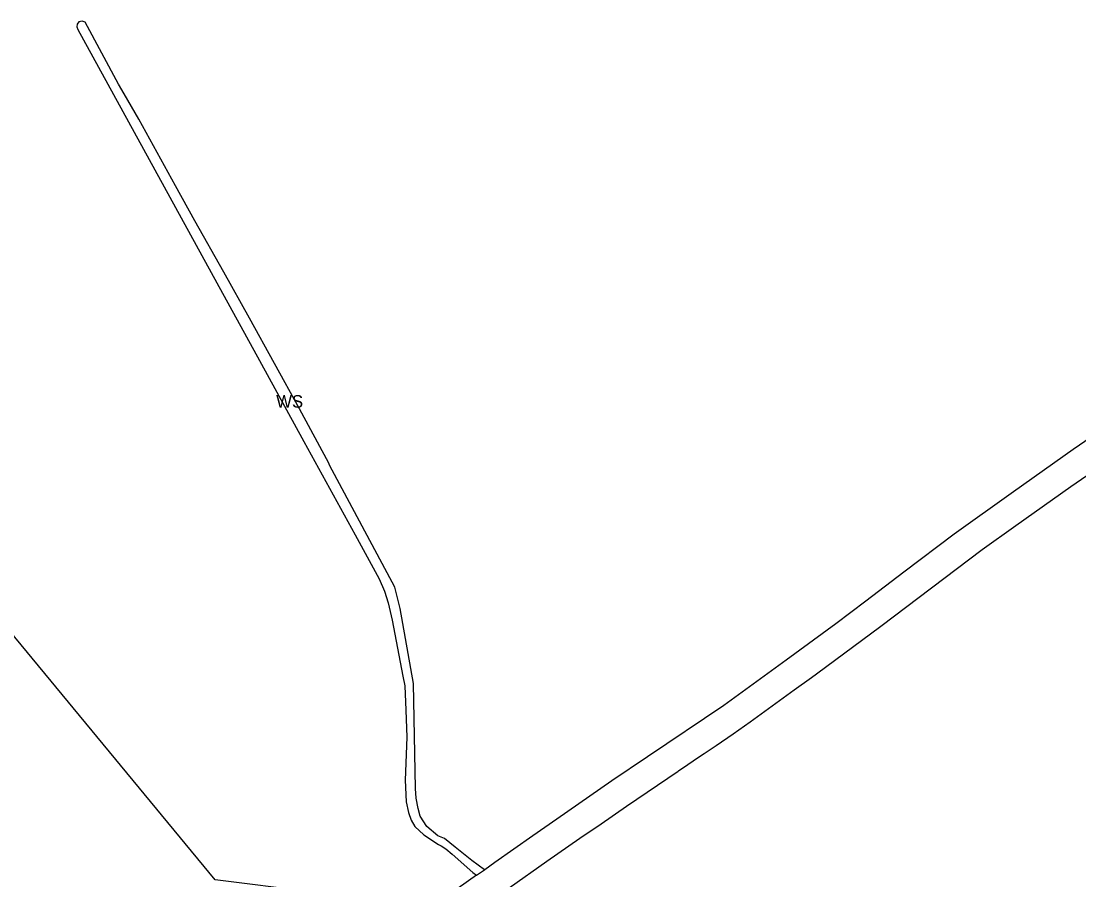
# Model space of a CAD drawing. Extents: x 7435758 to 7439981, y 5550649 to 5554049.
# Drawn here: x 7437632.3 to 7438071.5, y 5551959.4 to 5552316 of the extents above; entities that cross this region are included whole.
import ezdxf

# ---------------------------------------------------------------- set-up
doc = ezdxf.new("R2010")
doc.units = 0
doc.layers.add('linie_rozgraniczające', color=7, linetype='Continuous')
doc.layers.add('oznaczenia_przeznaczen', color=7, linetype='Continuous')

msp = doc.modelspace()

# ---------------------------------------------------------------- linework, layer by layer
at = {"layer": 'linie_rozgraniczające'}
for p, q in [((7437655.54, 5552314.73), (7437655.41, 5552313.64)), ((7437655.41, 5552313.64), (7437655.82, 5552312.48)), ((7437656.32, 5552315.76), (7437655.54, 5552314.73)), ((7437657.66, 5552315.99), (7437656.32, 5552315.76)), ((7437658.85, 5552315.59), (7437657.66, 5552315.99)), ((7437672.77, 5552289.88), (7437658.85, 5552315.59)), ((7437655.82, 5552312.48), (7437676.89, 5552274.12)), ((7437675.01, 5552285.82), (7437672.77, 5552289.88)), ((7437681.11, 5552275.27), (7437675.01, 5552285.82)), ((7437676.89, 5552274.12), (7437713.49, 5552207.37)), ((7437696.41, 5552247.65), (7437681.11, 5552275.27)), ((7437704.46, 5552233.13), (7437696.41, 5552247.65)), ((7437716.46, 5552211.77), (7437704.46, 5552233.13)), ((7437727.15, 5552192.6), (7437716.46, 5552211.77)), ((7437713.49, 5552207.37), (7437731.24, 5552175.15)), ((7437747.82, 5552154.95), (7437727.15, 5552192.6)), ((7437731.24, 5552175.15), (7437749.69, 5552141.43)), ((7437760, 5552132.4), (7437747.82, 5552154.95)), ((7438088.61, 5552151.62), (7438069.13, 5552138.13)), ((7437749.69, 5552141.43), (7437770.97, 5552102.66)), ((7438068.22, 5552122.79), (7438098, 5552143.5)), ((7438069.13, 5552138.13), (7438044.29, 5552120.56)), ((7437760.4, 5552131.68), (7437760, 5552132.4)), ((7437787.5, 5552080.98), (7437760.4, 5552131.68)), ((7437712.83, 5551959.48), (7437577.43, 5552123.38)), ((7438044.29, 5552120.56), (7438019.76, 5552103)), ((7438045.32, 5552106.59), (7438068.22, 5552122.79)), ((7438031.31, 5552096.54), (7438045.32, 5552106.59)), ((7437770.97, 5552102.66), (7437781.02, 5552084.36)), ((7438019.76, 5552103), (7437998.76, 5552087.24)), ((7437989.26, 5552064.78), (7438031.31, 5552096.54)), ((7437781.02, 5552084.36), (7437783.21, 5552079.3)), ((7437998.76, 5552087.24), (7437983.05, 5552075.14)), ((7437789.65, 5552072.11), (7437787.5, 5552080.98)), ((7437783.21, 5552079.3), (7437784.67, 5552074.52)), ((7437784.67, 5552074.52), (7437786.41, 5552067.27)), ((7437795.23, 5552040.98), (7437789.65, 5552072.11)), ((7437983.05, 5552075.14), (7437970.58, 5552065.72)), ((7437786.41, 5552067.27), (7437790.79, 5552044.05)), ((7437970.58, 5552065.72), (7437949.92, 5552050.67)), ((7437962.53, 5552045.04), (7437989.26, 5552064.78)), ((7437949.92, 5552050.67), (7437924.09, 5552031.87)), ((7437960.46, 5552043.51), (7437962.53, 5552045.04)), ((7437790.79, 5552044.05), (7437791.58, 5552039.97)), ((7437796.11, 5551997.41), (7437795.23, 5552040.98)), ((7437953.31, 5552038.3), (7437960.46, 5552043.5)), ((7437960.46, 5552043.5), (7437960.46, 5552043.51)), ((7437791.58, 5552039.97), (7437791.99, 5552029.95)), ((7437935.04, 5552024.99), (7437953.31, 5552038.3)), ((7437924.09, 5552031.87), (7437892.36, 5552010.52)), ((7437791.99, 5552029.95), (7437792.45, 5552018.67)), ((7437927.96, 5552020.01), (7437935.04, 5552024.99)), ((7437792.45, 5552018.67), (7437791.72, 5552000.89)), ((7437920.87, 5552015.23), (7437927.96, 5552020.01)), ((7437915.95, 5552011.93), (7437920.87, 5552015.23)), ((7437892.36, 5552010.52), (7437877.64, 5552000.61)), ((7437911.95, 5552009.24), (7437915.95, 5552011.93)), ((7437905.45, 5552004.86), (7437906.93, 5552005.82)), ((7437906.93, 5552005.82), (7437911.34, 5552008.83)), ((7437911.34, 5552008.83), (7437911.36, 5552008.84)), ((7437911.36, 5552008.84), (7437911.95, 5552009.24)), ((7437791.72, 5552000.89), (7437792.18, 5551991.78)), ((7437883.68, 5551990.07), (7437905.05, 5552004.59)), ((7437905.05, 5552004.59), (7437905.45, 5552004.86)), ((7437796.28, 5551993.3), (7437796.11, 5551997.41)), ((7437877.64, 5552000.61), (7437854.78, 5551984.69)), ((7437797.12, 5551989.1), (7437796.28, 5551993.3)), ((7437792.18, 5551991.78), (7437793.09, 5551987.39)), ((7437797.95, 5551985.86), (7437797.12, 5551989.1)), ((7437873.1, 5551982.72), (7437883.68, 5551990.07)), ((7437793.09, 5551987.39), (7437794.21, 5551984.18)), ((7437794.21, 5551984.18), (7437795.76, 5551981.53)), ((7437800.76, 5551981.58), (7437797.95, 5551985.86)), ((7437854.78, 5551984.69), (7437844.78, 5551977.68)), ((7437795.76, 5551981.53), (7437799.51, 5551978.16)), ((7437805.36, 5551977.76), (7437800.76, 5551981.58)), ((7437864.27, 5551976.69), (7437873.1, 5551982.72)), ((7437799.51, 5551978.16), (7437805.64, 5551974.16)), ((7437808.05, 5551976.66), (7437805.36, 5551977.76)), ((7437812.58, 5551972.99), (7437808.05, 5551976.66)), ((7437844.78, 5551977.68), (7437828.97, 5551966.61)), ((7437850.63, 5551967.13), (7437864.27, 5551976.69)), ((7437805.64, 5551974.16), (7437806.67, 5551973.51)), ((7437806.67, 5551973.51), (7437808.61, 5551972.29)), ((7437808.61, 5551972.29), (7437811.23, 5551970.05)), ((7437819.46, 5551967.45), (7437812.58, 5551972.99)), ((7437811.23, 5551970.05), (7437819.85, 5551962.54)), ((7437824.7, 5551963.61), (7437819.46, 5551967.45)), ((7437828.97, 5551966.61), (7437824.78, 5551963.66)), ((7437834.89, 5551956.1), (7437850.63, 5551967.13)), ((7437819.85, 5551962.54), (7437821.43, 5551961.32)), ((7437821.43, 5551961.32), (7437824.7, 5551963.61)), ((7437824.78, 5551963.66), (7437824.7, 5551963.61)), ((7437802.61, 5551948.27), (7437712.83, 5551959.48)), ((7437821.43, 5551961.32), (7437813.73, 5551955.92))]:
    msp.add_line(p, q, dxfattribs=at)

# ---------------------------------------------------------------- texts
at = {"layer": 'oznaczenia_przeznaczen'}
msp.add_text('WS', height=5.2, dxfattribs=at).set_placement((7437738.2, 5552155.5))

doc.saveas('drawing.dxf')
